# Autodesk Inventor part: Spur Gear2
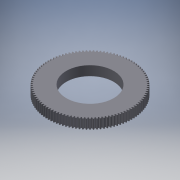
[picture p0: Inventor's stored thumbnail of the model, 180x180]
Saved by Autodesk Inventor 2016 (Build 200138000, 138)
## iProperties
Created: 2016-10
Part Number: Spur Gear2
Material: Steel
Document SubType Name: Modeling
Designer: Ingenieria
Categories: <?xml version="1.0" encoding="UTF-16"?> <MemberInstance><Categories><FamilyTemplate><FamilyTemplateParameter ValueType="xs:double" Id="1" ObjectReferenceKey="da
Density: 1 g/cm^3
Appearance: Steel
CustomPartVersion: 1
Author: Ingenieria
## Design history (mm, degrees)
sketch "Sketch1"
  geometry: C1 r 266.187 at (0, 0)
  constraints: 1 centre point
  dimensions: "d0" = 532.37337 diameter of C1 (= da_da)
extrude "Extrusion1" new body sketch "Sketch1" distance "d1" = 60 (= da_b); taper "d2" = 0 deg
workplane "Work Plane2"
sketch "Sketch2"
  geometry: C1 r 266.187 at (0, 0) reference; C2 r 261.193 at (0, 0)
  constraints: 1 centre point, 1 coincident
  dimensions: "d3" = 522.38588 diameter of C2 (= da_dw)
feature "Pitch Diameter" sketch "Sketch2" dims "d4" = 10, "d5" = 0
workplane "Work Plane8"
workplane "Work Plane9"
feature "Spur Gear" dims "d4" = 10, "d50" = 10, "d51" = 0, "da_b" = 60, "da_d" = 520, "da_aw" = 341.56, "da_da" = 532.37337, "da_df" = 509.92655, "da_dw" = 522.38588, angle "da_beta" = 0 deg, "da_lefttooth" = 0, "da_righttooth" = 0
sketch "Sketch3"
  geometry: C1 r 150 at (0, 0); 1 further point
  constraints: 1 centre point, 1 coincident
  dimensions: "d49" = 300 diameter of C1
extrude "Extrusion2" cut sketch "Sketch3" stored distance "d50" = 10; taper "d51" = 0 deg
body "Solid1"
body "Srf1"
other parameters: "d16" = 341.56 (= da_aw), "d17" = 0, "d34" = 0.30208 (computed from da_z), "d39" = 0, "d41" = 0, "d43" = 341.56 (= da_aw), "d46" = 341.56 (= da_aw), "d47" = 0, "d48" = 0
